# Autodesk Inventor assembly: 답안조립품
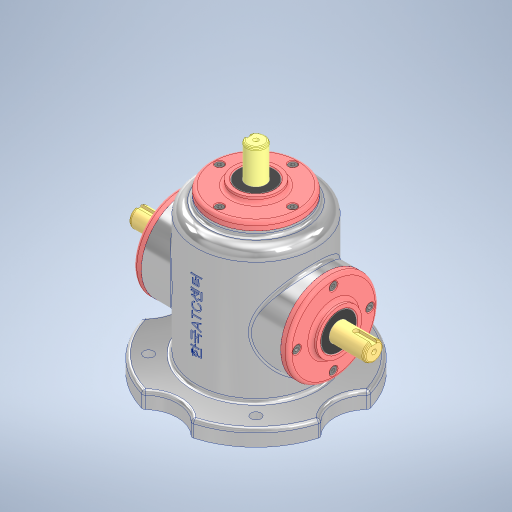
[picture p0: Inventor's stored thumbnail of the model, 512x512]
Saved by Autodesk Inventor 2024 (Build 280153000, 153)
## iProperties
Created: 2026-07
Part Number: 답안조립품
Document SubType Name: Assembly
Designer: com
Author: com
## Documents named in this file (12)
- C:\Users\com\Desktop\760703V1003\답안조립품.iam
- C:\Users\com\Desktop\760703V1003\6각 구멍붙이 볼트 M4x10\6각 구멍붙이 볼트 M4x10.ipt
- C:\Users\com\Desktop\760703V1003\깊은 홈 볼 베어링 6203\깊은 홈 볼 베어링 6203.ipt
- C:\Users\com\Desktop\760703V1003\메인 베벨기어\메인 베벨기어.ipt
- C:\Users\com\Desktop\760703V1003\메인 축\메인 축.ipt
- C:\Users\com\Desktop\760703V1003\서브 베벨기어\서브 베벨기어.ipt
- C:\Users\com\Desktop\760703V1003\서브 축\서브 축.ipt
- C:\Users\com\Desktop\760703V1003\오일 실 17 32 8\오일 실 17 32 8.ipt
- C:\Users\com\Desktop\760703V1003\커버\커버.ipt
- C:\Users\com\Desktop\760703V1003\평행 키 4x4x14\평행 키 4x4x14.ipt
- C:\Users\com\Desktop\760703V1003\평행 키 5x5x14\평행 키 5x5x14.ipt
- C:\Users\com\Desktop\760703V1003\본체.ipt
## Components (12 placed, 1 different names)
1. 6각 구멍붙이 볼트 M4x10:2
2. 6각 구멍붙이 볼트 M4x10:3
3. 6각 구멍붙이 볼트 M4x10:4
4. 6각 구멍붙이 볼트 M4x10:5
5. 6각 구멍붙이 볼트 M4x10:6
6. 6각 구멍붙이 볼트 M4x10:7
7. 6각 구멍붙이 볼트 M4x10:8
8. 6각 구멍붙이 볼트 M4x10:9
9. 6각 구멍붙이 볼트 M4x10:1
10. 6각 구멍붙이 볼트 M4x10:10
11. 6각 구멍붙이 볼트 M4x10:11
12. 6각 구멍붙이 볼트 M4x10:12
## Named parameters: d5_d3 = 0, d6_d4 = 0, d7_d3 = 0, d8_d4 = 0, d29_d22 = 0, d30_d23 = 0, d31_d24 = 0, d32_d25 = 0
